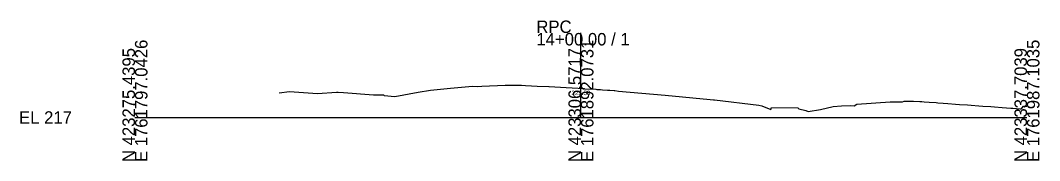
# Model space of a CAD drawing. Extents: x -26 to 203, y -10 to 4522.
# Drawn here: x -25.7 to 202.8, y 4490.3 to 4521.8 of the extents above; entities that cross this region are included whole.
import ezdxf

# ---------------------------------------------------------------- set-up
doc = ezdxf.new("R2010")
doc.units = 0
for name, color, linetype in [('Default', 7, 'Continuous'), ('Sheet Cross Section Grid Major CELL', 7, 'Continuous'), ('Sheet Cross Section Grid Middle CELL', 7, 'Continuous'), ('Sheet Cross Section Grid Minor 1 CELL', 7, 'Continuous')]:
    doc.layers.add(name, color=color, linetype=linetype)

msp = doc.modelspace()

# ---------------------------------------------------------------- linework, layer by layer
at = {"layer": 'Sheet Cross Section Grid Major CELL'}
for p, q in [((100, 4500), (100, 4518.99)), ((0, 4500), (100, 4500)), ((100, 4500), (200, 4500))]:
    msp.add_line(p, q, dxfattribs=at)
at = {"layer": 'Sheet Cross Section Grid Middle CELL'}
msp.add_lwpolyline([(32.35, 4505.54), (34.68, 4505.82), (40.9, 4505.41), (45.2, 4505.69), (45.59, 4505.72), (46.77, 4505.65), (53.52, 4505.08), (55.73, 4505.08), (55.91, 4504.94), (58.3, 4504.71), (63.51, 4505.66), (66.25, 4506.13), (70.77, 4506.6), (75.7, 4507.08), (76.91, 4507), (77.76, 4507.03), (83.03, 4507.26), (83.72, 4507.26), (83.9, 4507.27), (84.93, 4507.28), (84.95, 4507.28), (86.6, 4507.27), (86.63, 4507.27), (86.69, 4507.27), (87.57, 4507.22), (88.88, 4507.15), (90.19, 4507.08), (92.78, 4506.94), (92.81, 4506.94), (92.86, 4506.94), (95.43, 4506.79), (96.69, 4506.73), (98.05, 4506.65), (100.61, 4506.49), (100.68, 4506.49), (100.72, 4506.49), (100.83, 4506.48), (103.3, 4506.34), (103.56, 4506.32), (104.35, 4506.27), (104.83, 4506.24), (105.92, 4506.17), (106.48, 4506.13), (107.44, 4506.06), (107.57, 4506.05), (108.43, 4505.95), (111.01, 4505.72), (118.86, 4505.05), (128.98, 4504.05), (129.71, 4503.97), (129.77, 4503.97), (129.81, 4503.96), (129.92, 4503.94), (139.91, 4502.78), (140.55, 4502.62), (142.56, 4501.83), (142.69, 4502.26), (148.63, 4502.14), (148.85, 4501.93), (150.43, 4501.6), (150.95, 4501.33), (153.7, 4501.77), (156.56, 4502.51), (158.45, 4502.63), (160.39, 4502.69), (161.25, 4502.66), (161.84, 4503.03), (169.34, 4503.56), (172.06, 4503.56), (172.48, 4503.71), (172.68, 4503.7), (174.11, 4503.68), (174.36, 4503.67), (174.53, 4503.67), (175.95, 4503.63), (176.45, 4503.6), (176.99, 4503.55), (178.05, 4503.48), (179.65, 4503.36), (180.03, 4503.33), (181.2, 4503.24), (182.27, 4503.16), (183.98, 4503.03), (184.89, 4502.96), (186.68, 4502.82), (187.5, 4502.76), (189.19, 4502.63), (190.12, 4502.56), (191.88, 4502.44), (192.75, 4502.38), (194.48, 4502.25), (195.38, 4502.18), (196.36, 4502.11), (196.78, 4502.08), (196.86, 4502.08), (198.48, 4501.97), (198.65, 4501.96), (198.82, 4502.13), (199.2, 4502.52), (200, 4502.54)], dxfattribs=at)
msp.add_lwpolyline([(32.35, 4505.54), (34.68, 4505.82), (40.9, 4505.41), (45.2, 4505.69), (45.59, 4505.72), (46.77, 4505.65), (53.52, 4505.08), (55.73, 4505.08), (55.91, 4504.94), (58.3, 4504.71), (63.51, 4505.66), (66.25, 4506.13), (70.77, 4506.6), (75.7, 4507.08), (76.91, 4507), (77.76, 4507.03), (83.03, 4507.26), (83.72, 4507.26), (83.9, 4507.27), (84.93, 4507.28), (84.95, 4507.28), (86.6, 4507.27), (86.63, 4507.27), (86.69, 4507.27), (87.57, 4507.22), (88.88, 4507.15), (90.19, 4507.08), (92.78, 4506.94), (92.81, 4506.94), (92.86, 4506.94), (95.43, 4506.79), (96.69, 4506.73), (98.05, 4506.65), (100.61, 4506.49), (100.68, 4506.49), (100.72, 4506.49), (100.83, 4506.48), (103.3, 4506.34), (103.56, 4506.32), (104.35, 4506.27), (104.83, 4506.24), (105.92, 4506.17), (106.48, 4506.13), (107.44, 4506.06), (107.57, 4506.05), (108.43, 4505.95), (111.01, 4505.72), (118.86, 4505.05), (128.98, 4504.05), (129.71, 4503.97), (129.77, 4503.97), (129.81, 4503.96), (129.92, 4503.94), (139.91, 4502.78), (140.55, 4502.62), (142.56, 4501.83), (142.69, 4502.26), (148.63, 4502.14), (148.85, 4501.93), (150.43, 4501.6), (150.95, 4501.33), (153.7, 4501.77), (156.56, 4502.51), (158.45, 4502.63), (160.39, 4502.69), (161.25, 4502.66), (161.84, 4503.03), (169.34, 4503.56), (172.06, 4503.56), (172.48, 4503.71), (172.68, 4503.7), (174.11, 4503.68), (174.36, 4503.67), (174.53, 4503.67), (175.95, 4503.63), (176.45, 4503.6), (176.99, 4503.55), (178.05, 4503.48), (179.65, 4503.36), (180.03, 4503.33), (181.2, 4503.24), (182.27, 4503.16), (183.98, 4503.03), (184.89, 4502.96), (186.68, 4502.82), (187.5, 4502.76), (189.19, 4502.63), (190.12, 4502.56), (191.88, 4502.44), (192.75, 4502.38), (194.48, 4502.25), (195.38, 4502.18), (196.36, 4502.11), (196.78, 4502.08), (196.86, 4502.08), (198.48, 4501.97), (198.65, 4501.96), (198.82, 4502.13), (199.2, 4502.52), (200, 4502.54)], dxfattribs=at)

# ---------------------------------------------------------------- texts
at = {"layer": 'Default'}
msp.add_text('-', height=0.0001, dxfattribs=at).set_placement((0, 4500))
at = {"layer": 'Sheet Cross Section Grid Major CELL'}
for s, p in [('RPC', (90, 4518.99)), ('14+00.00 / 1', (90, 4516.19)), ('EL 217', (-26, 4498.6))]:
    msp.add_text(s, height=2.8, dxfattribs=at).set_placement(p)
for s, p in [('E 1761797.0426', (2.8, 4490)), ('E 1761892.0731', (102.8, 4490)), ('E 1761987.1035', (202.8, 4490)), ('N 423275.4395', (0, 4490)), ('N 423306.5717', (100, 4490)), ('N 423337.7039', (200, 4490))]:
    msp.add_text(s, height=2.8, rotation=90, dxfattribs=at).set_placement(p)
at = {"layer": 'Sheet Cross Section Grid Minor 1 CELL'}
msp.add_text('223.53', height=1, dxfattribs=at).set_placement((97.88, 4505.03))

doc.saveas('drawing.dxf')
